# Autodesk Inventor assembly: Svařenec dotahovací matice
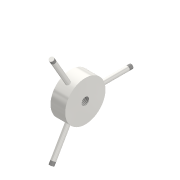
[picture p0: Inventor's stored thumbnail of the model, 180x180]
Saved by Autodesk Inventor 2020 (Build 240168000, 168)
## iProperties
Created: 2025-04
Part Number: Svařenec dotahovací matice
Document SubType Name: Assembly
Designer: doma
Mass: 367.851 g
Surface Area: 131.469 cm^2
Volume: 46.86 cm^3
Density: 7.85 g/cm^3
Author: doma
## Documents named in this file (3)
- C:\Users\doma\Desktop\Pásovka záloha\Workgroups\NotInProject\Svařenec dotahovací matice.iam
- C:\Users\doma\Desktop\Pásovka záloha\Workgroups\NotInProject\Matice napínání pásu.ipt
- C:\Users\doma\Desktop\Pásovka záloha\Workgroups\NotInProject\Vratidlo.ipt
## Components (4 placed, 2 different names)
1. Matice napínání pásu:1 — Proti sobě:7, Proti sobě:8, Proti sobě:9, Proti sobě:10, Proti sobě:11
2. Vratidlo:1 — Proti sobě:9
3. Vratidlo:2 — Proti sobě:11
4. Vratidlo:3 — Úhel:1, Proti sobě:10
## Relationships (6: Mate 5, Angle 1)
- Proti sobě:7 [Mate]: Matice napínání pásu:1
- Proti sobě:8 [Mate]: Matice napínání pásu:1
- Úhel:1 [Angle]: Vratidlo:3
- Proti sobě:9 [Mate]: Matice napínání pásu:1 ↔ Vratidlo:1
- Proti sobě:10 [Mate]: Matice napínání pásu:1 ↔ Vratidlo:3
- Proti sobě:11 [Mate]: Matice napínání pásu:1 ↔ Vratidlo:2
## Named parameters: d63_d208 = 0
